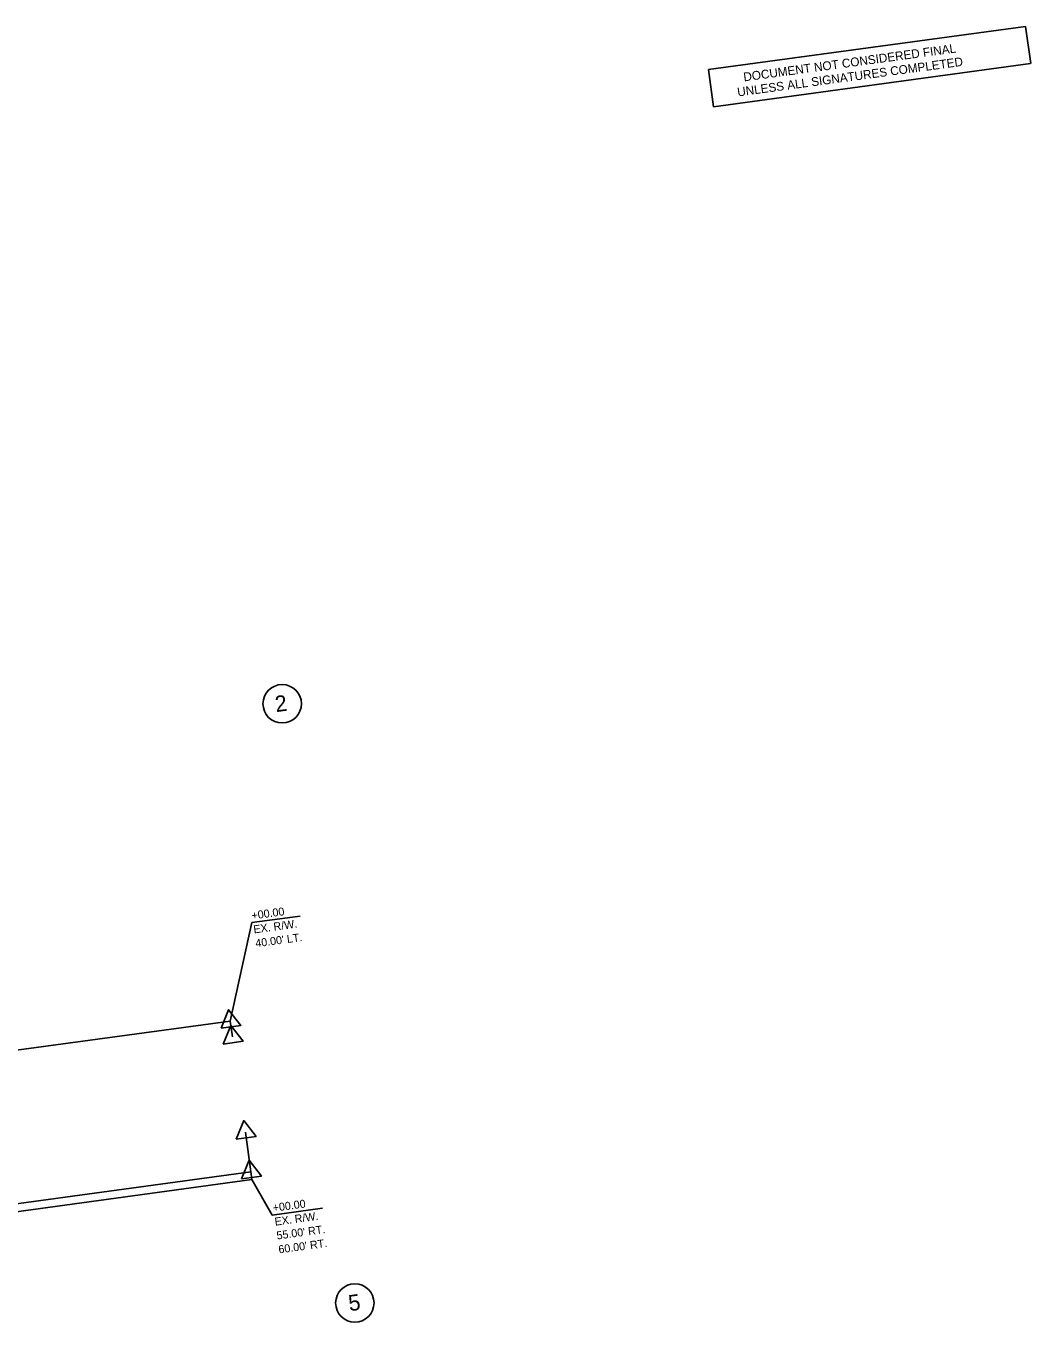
# Model space of a CAD drawing. Extents: x 2111254 to 2112709, y 581490 to 582407.
# Drawn here: x 2112082 to 2112709, y 581584 to 582407 of the extents above; entities that cross this region are included whole.
import ezdxf

# ---------------------------------------------------------------- set-up
doc = ezdxf.new("R2010")
doc.units = 0
for name, color, linetype in [('Prop Easement Construction', 7, 'Continuous'), ('Prop Parcel Number CELL', 7, 'Continuous'), ('Prop Parcel Number Text', 7, 'Continuous'), ('Prop ROW Marker CELL', 7, 'Continuous'), ('Prop ROW RW Lines', 7, 'Continuous'), ('Prop ROW Station Offsets', 7, 'Continuous'), ('Sheet Sticker Exception Certification CELL', 7, 'Continuous')]:
    doc.layers.add(name, color=color, linetype=linetype)

msp = doc.modelspace()

# ---------------------------------------------------------------- linework, layer by layer
at = {"layer": 'Prop Easement Construction'}
for p in [(2112221.87, 581690.77), (2111628.06, 581604.69)]:
    msp.add_line(p, (2112222.55, 581685.82), dxfattribs=at)
at = {"layer": 'Prop Parcel Number CELL'}
for p, q in [((2112241.49, 581983.2), (2112241.49, 581983.2)), ((2112286.89, 581608.74), (2112286.89, 581608.74))]:
    msp.add_line(p, q, dxfattribs=at)
for centre in [(2112241.49, 581983.2), (2112286.89, 581608.74)]:
    msp.add_circle(centre, 12, dxfattribs=at)
at = {"layer": 'Prop ROW Marker CELL'}
for p, q in [((2112209.03, 581784.9), (2112209.03, 581784.9)), ((2112210.38, 581774.99), (2112210.38, 581774.99)), ((2112218.49, 581715.54), (2112218.49, 581715.54)), ((2112221.87, 581690.77), (2112221.87, 581690.77))]:
    msp.add_line(p, q, dxfattribs=at)
for points in [[(2112203.32, 581780.49), (2112208.05, 581792.03), (2112215.71, 581782.18)], [(2112204.67, 581770.58), (2112209.4, 581782.13), (2112217.06, 581772.27)], [(2112212.79, 581711.13), (2112217.52, 581722.68), (2112225.17, 581712.82)], [(2112216.17, 581686.36), (2112220.9, 581697.91), (2112228.55, 581688.05)]]:
    msp.add_lwpolyline(points, close=True, dxfattribs=at)
at = {"layer": 'Prop ROW RW Lines'}
for p, q in [((2112060.4, 581764.62), (2112209.03, 581784.9)), ((2112209.03, 581784.9), (2112210.38, 581774.99)), ((2112218.49, 581715.54), (2112221.87, 581690.77)), ((2111438.99, 581583.93), (2112221.87, 581690.77))]:
    msp.add_line(p, q, dxfattribs=at)
at = {"layer": 'Prop ROW Station Offsets'}
for p, q in [((2112222.46, 581846.42), (2112209.03, 581784.9)), ((2112252.73, 581850.55), (2112222.46, 581846.42)), ((2112266.73, 581668), (2112235.33, 581663.71))]:
    msp.add_line(p, q, dxfattribs=at)
msp.add_lwpolyline([(2112235.33, 581663.71), (2112222.55, 581685.82)], dxfattribs=at)
at = {"layer": 'Sheet Sticker Exception Certification CELL'}
for p, q in [((2112507.77, 582379.53), (2112705.97, 582406.57)), ((2112705.97, 582406.56), (2112709.15, 582383.28)), ((2112709.14, 582383.29), (2112510.94, 582356.24)), ((2112510.94, 582356.24), (2112507.77, 582379.53))]:
    msp.add_line(p, q, dxfattribs=at)

# ---------------------------------------------------------------- texts
at = {"layer": 'Prop Parcel Number Text'}
for s, p in [('2', (2112237.71, 581977.97)), ('5', (2112283.57, 581603.57))]:
    msp.add_text(s, height=10, rotation=7.77101, dxfattribs=at).set_placement(p)
at = {"layer": 'Prop ROW Station Offsets'}
for s, p in [('+00.00', (2112222.69, 581848.34)), ('EX. R/W.', (2112223.88, 581839.67)), ("40.00' LT.", (2112225.06, 581831)), ('+00.00', (2112235.94, 581665.69)), ('EX. R/W.', (2112237.12, 581657.02)), ("55.00' RT.", (2112238.31, 581648.35)), ("60.00' RT.", (2112239.49, 581639.68))]:
    msp.add_text(s, height=5, rotation=7.77101, dxfattribs=at).set_placement(p)
at = {"layer": 'Sheet Sticker Exception Certification CELL'}
for s, p in [('DOCUMENT NOT CONSIDERED FINAL', (2112530.04, 582372.12)), ('UNLESS ALL SIGNATURES COMPLETED', (2112526.21, 582362.72))]:
    msp.add_text(s, height=5.5, rotation=7.77101, dxfattribs=at).set_placement(p)

doc.saveas('drawing.dxf')
